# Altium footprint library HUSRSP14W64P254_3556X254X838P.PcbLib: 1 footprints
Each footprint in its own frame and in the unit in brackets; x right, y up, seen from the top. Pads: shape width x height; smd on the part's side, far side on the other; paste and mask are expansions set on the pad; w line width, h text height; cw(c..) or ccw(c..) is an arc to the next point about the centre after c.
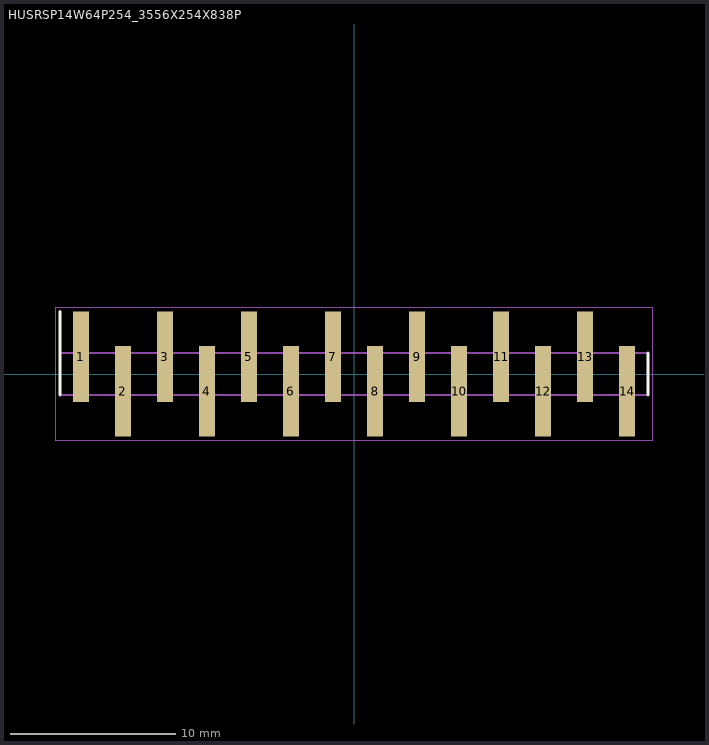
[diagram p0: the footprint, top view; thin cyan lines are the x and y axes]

## HUSRSP14W64P254_3556X254X838P [mm]
pads (14):
  rect 0.96x5.46 smd: 1(-16.51,1.045) 2(-13.97,-1.045) 3(-11.43,1.045) 4(-8.89,-1.045) 5(-6.35,1.045) 6(-3.81,-1.045) 7(-1.27,1.045) 8(1.27,-1.045) 9(3.81,1.045) 10(6.35,-1.045) 11(8.89,1.045) 12(11.43,-1.045) 13(13.97,1.045) 14(16.51,-1.045)
Top Overlay:
  lines w0.2: -17.78,-1.27 -17.78,3.775 ; 17.78,-1.27 17.78,1.27
Mechanical 15:
  lines w0.1: -17.78,-1.27 17.78,-1.27 17.78,1.27 -17.78,1.27 -17.78,-1.27
Mechanical 20:
  lines w0.05: -18.03,-4.025 18.03,-4.025 18.03,4.025 -18.03,4.025 -18.03,-4.025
